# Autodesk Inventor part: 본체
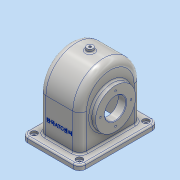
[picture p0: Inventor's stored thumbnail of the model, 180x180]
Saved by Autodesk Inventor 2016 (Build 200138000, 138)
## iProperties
Created: 2018-11
Part Number: 본체
Material: 알루미늄 6061
Document SubType Name: Modeling
Designer: user
Density: 2.7 g/cm^3
Appearance: 알루미늄 - 평지
Mass: 1092.08 g
Surface Area: 1182.21 cm^2
Volume: 404.475 cm^3
Author: user
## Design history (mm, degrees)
sketch "스케치1"
  geometry: L1 (-55, -75)-(55, -75); L2 (55, -75)-(55, 75); L3 (55, 75)-(-55, 75); L4 (-55, 75)-(-55, -75); L5 (-55, -75)-(55, 75); L6 (55, -75)-(-55, 75); 1 further point
  constraints: 12 end point, 2 midpoint, 2 parallel, 1 horizontal, 1 perpendicular
  dimensions: "d0" = 110 distance of L3.end L2.end; "d1" = 150 distance of L2.end L1.end
extrude "돌출1" new body sketch "스케치1" distance "d2" = 10; taper "d3" = 0 deg
sketch "스케치2"
  geometry: L1 (-38.5, -58)-(38.5, -58); L2 (38.5, -58)-(38.5, 58); L3 (38.5, 58)-(-38.5, 58); L4 (-38.5, 58)-(-38.5, -58); L5 (-38.5, -58)-(38.5, 58); L6 (38.5, -58)-(-38.5, 58); 1 further point
  constraints: 12 end point, 2 midpoint, 2 parallel, 1 horizontal, 1 perpendicular
  dimensions: "d4" = 77 distance of L2.end L3.end; "d5" = 116 distance of L1.end L2.end
extrude "돌출2" join sketch "스케치2" distance "d6" = 126; taper "d7" = 0 deg
fillet "모깎기1" dims "d8" = 58
feature "쉘1" dims "d10" = 5, "d11" = 10, "d27" = 6
node "작업 평면1"
sketch "스케치3"
  geometry: C1 r 6 at (0, 0); 1 further point
  constraints: 1 centre point, 1 coincident
  dimensions: "d13" = 12 diameter of C1
extrude "돌출3" join sketch "스케치3" stored distance "d14" = 126; taper "d15" = 5 deg
sketch "스케치4"
  geometry: 2 further points
  constraints: 1 coincident
hole "구멍1" sketch "스케치4" at (0, 0) diameter "d16" = 4.459; stored, may be unused: countersink angle "d20" = 90 deg, drill point angle "d22" = 118 deg; dims "d17" = 30, "d18" = 4, "d19" = 2, "d21" = 32.8
sketch "스케치5"
  geometry: L1 (0, 103)-(68, 103) reference; L2 (-10, 97)-(-10, -7) reference; C1 r 38 at (55, 45)
  constraints: 1 centre point
  dimensions: "d23" = 76 diameter of C1; "d82" = 58 distance from line of L1 C1.centre; "d83" = 65 distance from line of L2 C1.centre
extrude "돌출4" join sketch "스케치5" distance "d25" = 5; taper "d26" = 0 deg
sketch "스케치7"
  geometry: L1 (10, -17)-(10, 133) reference; C1 r 38 at (-55, 58); 2 further points
  constraints: 1 centre point, 1 horizontal alignment, 1 midpoint
  dimensions: "d29" = 76 diameter of C1; "d30" = 65 distance from line of L1 C1.centre
extrude "돌출5" join sketch "스케치7" distance "d31" = 10; taper "d32" = 0 deg
node "작업 평면2"
sketch "스케치9"
  geometry: C1 r 28 at (0, 0); 1 further point
  constraints: 1 centre point, 1 horizontal alignment
  dimensions: "d36" = 65 distance of C1.centre point (-65, 0); "d37" = 56 diameter of C1
extrude "돌출6" join sketch "스케치9" stored distance "d38" = 24; taper "d39" = 40 deg
sketch "스케치10"
  geometry: C1 r 20 at (0, 0); C2 r 38 at (0, 0) reference; 1 further point
  constraints: 1 centre point, 1 concentric
  dimensions: "d40" = 40 diameter of C1
extrude "돌출7" cut sketch "스케치10" distance "d41" = 100; taper "d42" = 0 deg
sketch "스케치11"
  geometry: L1 (-65, 75)-(-65, -75) reference; 3 further points
  constraints: 1 horizontal alignment, 1 midpoint
  dimensions: "d43" = 94 distance from line of L1 point (29, 0)
hole "구멍2" sketch "스케치11" at (29, 0) diameter "d44" = 3.242; stored, may be unused: countersink angle "d48" = 90 deg, drill point angle "d50" = 118 deg; dims "d45" = 8, "d46" = 4, "d47" = 2, "d49" = 10
sketch "스케치12"
  geometry: L1 (65, -75)-(65, 75) reference; 3 further points
  constraints: 1 horizontal alignment, 1 midpoint
  dimensions: "d54" = 94 distance from line of point (-29, 0) L1
hole "구멍3" sketch "스케치12" at (-29, 0) diameter "d55" = 3.242; stored, may be unused: countersink angle "d59" = 90 deg, drill point angle "d61" = 118 deg; dims "d56" = 8, "d57" = 4, "d58" = 2, "d60" = 10
fillet "모깎기3" dims "d65" = 12, "d66" = 13
fillet "모깎기4" dims "d67" = 8
fillet "모깎기5" dims "d68" = 3
sketch "스케치13"
  geometry: C1 r 6 at (-43, -63); A1 r 12 centre (-43, -63) between (-55, -63) and (-43, -75) reference; 1 further point
  constraints: 1 centre point, 1 coincident
  dimensions: "d69" = 12 diameter of C1
extrude "돌출8" cut sketch "스케치13" distance "d70" = 4; taper "d71" = 0 deg
sketch "스케치14"
  geometry: C1 r 2.5 at (0, 0); C2 r 6 at (0, 0) reference; 1 further point
  constraints: 1 centre point, 1 concentric
  dimensions: "d72" = 5 diameter of C1
extrude "돌출9" cut sketch "스케치14" distance "d73" = 20; taper "d74" = 0 deg
sketch "스케치15"
  geometry: L1 (-17.5, -78)-(-29.5, -78) reference; L2 (-13, 0)-(-13, -65) reference; 2 further points
  constraints: 1 other
  dimensions: "d75" = 40 distance from line of L1 point (25.5, -38); "d76" = 38.5 distance from line of L2 point (25.5, -38)
feature "엠보싱1" sketch "스케치15" dims "d0" = 110, "d1" = 150, "d77" = 0.5, "d78" = 0
chamfer "모따기1" distance "d79" = 1; stored, may be unused: second distance "d80" = 2, angle "d81" = 45 deg
node "솔리드1"
pattern_circular "원형 패턴1" dims angle "d52" = 360 deg
pattern_circular "원형 패턴2" dims angle "d63" = 360 deg
mirror "대칭1"
mirror "대칭2"
other parameters: "d12" = -142, "d35" = -24
